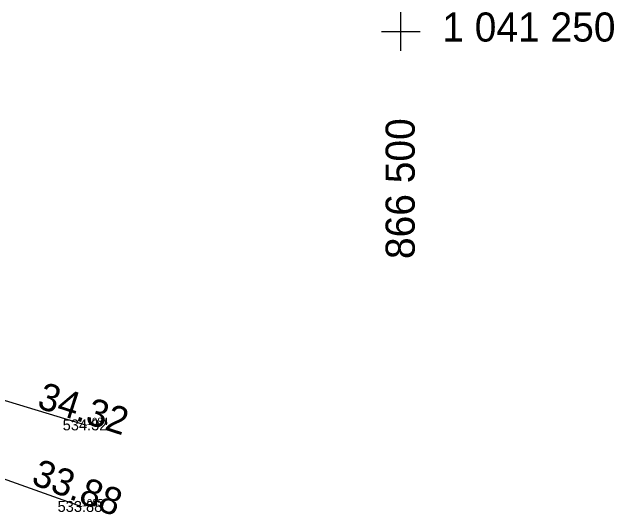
# Model space of a CAD drawing. Extents: x -866693 to -866303, y -1041966 to -1040244.
# Drawn here: x -866510.68 to -866494.15, y -1041263.28 to -1041249.47 of the extents above; entities that cross this region are included whole.
import ezdxf

# ---------------------------------------------------------------- set-up
doc = ezdxf.new("R2010")
doc.units = 0
for name, color, linetype in [('1 hrana zpevněné komunikace-plocha', 7, 'Continuous'), ('8 hrana svah dole', 7, 'Continuous'), ('Bod', 7, 'Continuous'), ('Nadmořská výška', 7, 'Continuous'), ('Nadmořská výška_tisk', 7, 'Continuous'), ('Síť', 7, 'Continuous'), ('Síť křížek', 7, 'Continuous'), ('Číslo bodu', 7, 'Continuous')]:
    doc.layers.add(name, color=color, linetype=linetype)

msp = doc.modelspace()

# ---------------------------------------------------------------- linework, layer by layer
at = {"layer": '1 hrana zpevněné komunikace-plocha'}
msp.add_line((-866526.559, -1041255.381), (-866508.635, -1041260.814), dxfattribs=at)
at = {"layer": '8 hrana svah dole'}
msp.add_line((-866526.628, -1041256.733), (-866508.775, -1041263.048), dxfattribs=at)
at = {"layer": 'Bod'}
for p, q in [((-866508.635, -1041260.814), (-866508.635, -1041260.814)), ((-866508.775, -1041263.048), (-866508.775, -1041263.048))]:
    msp.add_line(p, q, dxfattribs=at)
at = {"layer": 'Síť křížek'}
for p, q in [((-866500, -1041250.53), (-866500, -1041249.47)), ((-866500.53, -1041250), (-866499.47, -1041250))]:
    msp.add_line(p, q, dxfattribs=at)

# ---------------------------------------------------------------- texts
at = {"layer": 'Nadmořská výška'}
for s, p in [('534.32', (-866509.29, -1041260.96)), ('533.88', (-866509.43, -1041263.2))]:
    msp.add_text(s, height=0.3, dxfattribs=at).set_placement(p)
at = {"layer": 'Nadmořská výška_tisk'}
for s, rotation, p in [('34.32', 342.1136, (-866510.026, -1041260.332)), ('33.88', 338.6204, (-866510.186, -1041262.42))]:
    msp.add_text(s, height=0.75, rotation=rotation, dxfattribs=at).set_placement(p)
at = {"layer": 'Síť'}
msp.add_text('1 041 250', height=0.8, dxfattribs=at).set_placement((-866498.864, -1041250.279))
msp.add_text('866 500', height=0.8, rotation=90, dxfattribs=at).set_placement((-866499.62, -1041256.253))
at = {"layer": 'Číslo bodu'}
for s, p in [('1084', (-866508.635, -1041260.814)), ('1085', (-866508.775, -1041263.048))]:
    msp.add_text(s, height=0.2, dxfattribs=at).set_placement(p)

doc.saveas('drawing.dxf')
